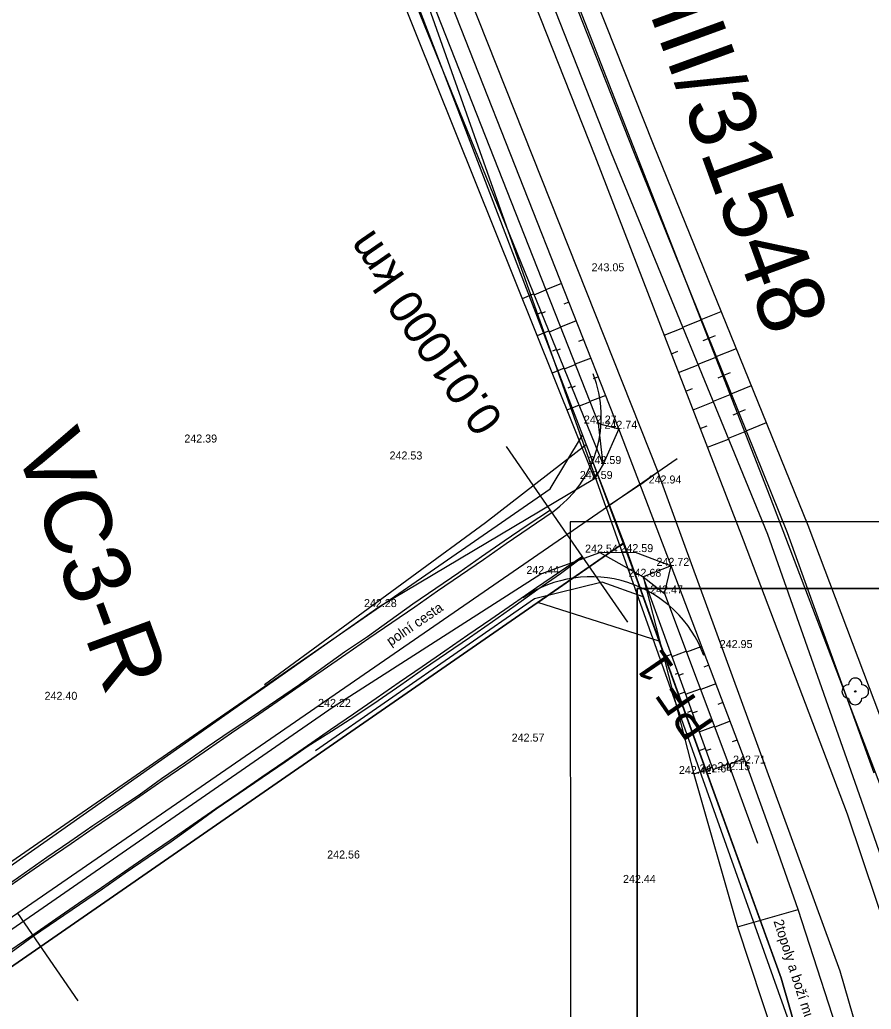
# Model space of a CAD drawing. Extents: x -555887 to -552101, y -1100251 to -1096546.
# Drawn here: x -554780.1 to -554716.3, y -1098267.2 to -1098193.1 of the extents above; entities that cross this region are included whole.
import ezdxf

# ---------------------------------------------------------------- set-up
doc = ezdxf.new("R2010")
doc.units = 0
for name, color, linetype in [('PARCELY_cesty', 7, 'Continuous'), ('PARCELY_silnice', 7, 'Continuous'), ('POLYGONY_rozšíření', 7, 'Continuous'), ('POLYGONY_SITUACE_PF', 7, 'Continuous'), ('POLYGONY_SITUACE_PF_POPISY', 7, 'Continuous'), ('POLYGONY_SITUACE_PO', 7, 'Continuous'), ('ram_VC5', 7, 'Continuous'), ('ROZHLED_parcela_cesty', 7, 'Continuous'), ('ROZHLED_ram_legenda_2', 7, 'Continuous'), ('ROZHLED_trojuhelniky_2', 7, 'Continuous'), ('Výškopis', 7, 'Continuous'), ('ZSST', 7, 'Continuous'), ('zájem', 7, 'Continuous')]:
    doc.layers.add(name, color=color, linetype=linetype)

msp = doc.modelspace()

# ---------------------------------------------------------------- linework, layer by layer
at = {"layer": 'PARCELY_cesty'}
for points in [[(-555432.8, -1098748.4), (-555400.008, -1098712.208), (-555389.921, -1098701.565), (-555373.936, -1098686.469), (-555357.132, -1098672.276), (-555340.17, -1098659.659), (-555299.833, -1098630.198), (-555259.851, -1098600.294), (-555132.603, -1098503.989), (-555074.98, -1098461.38), (-555070.799, -1098455.669), (-555054.379, -1098443.798), (-555047.89, -1098441.68), (-555024.771, -1098425.173), (-554988.252, -1098399.708), (-554740.35, -1098228.23), (-554737.92, -1098224.21)], [(-554741.27, -1098236.74), (-554734.83, -1098232.28), (-554732.18, -1098239.65), (-554741.27, -1098236.74)]]:
    msp.add_lwpolyline(points, dxfattribs=at)
at = {"layer": 'PARCELY_silnice'}
msp.add_lwpolyline([(-554799.78, -1098062.8), (-554737.92, -1098224.21), (-554734.83, -1098232.28), (-554723.03, -1098264.9), (-554699.69, -1098346.16), (-554674.86, -1098437.73), (-554672.03, -1098436.78), (-554666.38, -1098434.92), (-554663.87, -1098434.13), (-554711.41, -1098261.44), (-554723.86, -1098228.82), (-554789.41, -1098060.89)], dxfattribs=at)
at = {"layer": 'POLYGONY_rozšíření'}
for centre, radius, start, end in [((-554745.264, -1098222.852), 8.754, 305.29041, 21.67407), ((-554737.283, -1098243.816), 9, 20.08231, 124.42283)]:
    msp.add_arc(centre, radius, start, end, dxfattribs=at)
at = {"layer": 'POLYGONY_SITUACE_PF'}
for p, q in [((-554739.072, -1098231.645), (-554743.611, -1098225.057)), ((-554734.532, -1098238.232), (-554739.072, -1098231.645)), ((-554775.704, -1098266.603), (-554780.243, -1098260.016))]:
    msp.add_line(p, q, dxfattribs=at)
at = {"layer": 'POLYGONY_SITUACE_PO'}
for p, q in [((-554730.837, -1098225.971), (-554986.543, -1098402.174)), ((-554740.322, -1098229.831), (-554742.07, -1098230.966)), ((-554740.206, -1098229.998), (-554741.922, -1098231.18)), ((-554740.206, -1098229.998), (-554741.922, -1098231.18)), ((-554742.07, -1098230.966), (-554743.79, -1098232.141)), ((-554741.922, -1098231.18), (-554743.637, -1098232.362)), ((-554741.922, -1098231.18), (-554743.637, -1098232.362)), ((-554743.79, -1098232.141), (-554745.497, -1098233.335)), ((-554743.637, -1098232.362), (-554745.353, -1098233.544)), ((-554743.637, -1098232.362), (-554745.353, -1098233.544)), ((-554745.497, -1098233.335), (-554747.199, -1098234.536)), ((-554745.353, -1098233.544), (-554747.068, -1098234.726)), ((-554745.353, -1098233.544), (-554747.068, -1098234.726)), ((-554737.937, -1098233.292), (-554739.652, -1098234.474)), ((-554737.937, -1098233.292), (-554739.652, -1098234.474)), ((-554737.9, -1098233.345), (-554739.562, -1098234.605)), ((-554747.199, -1098234.536), (-554748.922, -1098235.708)), ((-554739.652, -1098234.474), (-554741.368, -1098235.656)), ((-554739.652, -1098234.474), (-554741.368, -1098235.656)), ((-554739.562, -1098234.605), (-554741.279, -1098235.785)), ((-554747.068, -1098234.726), (-554748.784, -1098235.909)), ((-554747.068, -1098234.726), (-554748.784, -1098235.909)), ((-554748.922, -1098235.708), (-554750.642, -1098236.884)), ((-554748.784, -1098235.909), (-554750.499, -1098237.091)), ((-554748.784, -1098235.909), (-554750.499, -1098237.091)), ((-554741.368, -1098235.656), (-554743.083, -1098236.838)), ((-554741.368, -1098235.656), (-554743.083, -1098236.838)), ((-554741.279, -1098235.785), (-554742.978, -1098236.991)), ((-554750.642, -1098236.884), (-554752.335, -1098238.099)), ((-554743.083, -1098236.838), (-554744.799, -1098238.02)), ((-554743.083, -1098236.838), (-554744.799, -1098238.02)), ((-554750.499, -1098237.091), (-554752.215, -1098238.273)), ((-554750.499, -1098237.091), (-554752.215, -1098238.273)), ((-554742.978, -1098236.991), (-554744.674, -1098238.201)), ((-554752.335, -1098238.099), (-554754.028, -1098239.313)), ((-554752.215, -1098238.273), (-554753.93, -1098239.455)), ((-554752.215, -1098238.273), (-554753.93, -1098239.455)), ((-554744.799, -1098238.02), (-554746.514, -1098239.202)), ((-554744.799, -1098238.02), (-554746.514, -1098239.202)), ((-554744.674, -1098238.201), (-554746.383, -1098239.393)), ((-554754.028, -1098239.313), (-554755.76, -1098240.471)), ((-554753.93, -1098239.455), (-554755.646, -1098240.637)), ((-554753.93, -1098239.455), (-554755.646, -1098240.637)), ((-554746.514, -1098239.202), (-554748.23, -1098240.384)), ((-554746.514, -1098239.202), (-554748.23, -1098240.384)), ((-554746.383, -1098239.393), (-554748.104, -1098240.566)), ((-554755.76, -1098240.471), (-554757.445, -1098241.698)), ((-554748.23, -1098240.384), (-554749.945, -1098241.567)), ((-554748.23, -1098240.384), (-554749.945, -1098241.567)), ((-554748.104, -1098240.566), (-554749.83, -1098241.734)), ((-554755.646, -1098240.637), (-554757.361, -1098241.819)), ((-554755.646, -1098240.637), (-554757.361, -1098241.819)), ((-554757.445, -1098241.698), (-554759.133, -1098242.919)), ((-554757.361, -1098241.819), (-554759.077, -1098243.001)), ((-554757.361, -1098241.819), (-554759.077, -1098243.001)), ((-554749.945, -1098241.567), (-554751.661, -1098242.749)), ((-554749.945, -1098241.567), (-554751.661, -1098242.749)), ((-554749.83, -1098241.734), (-554751.533, -1098242.934)), ((-554751.661, -1098242.749), (-554753.376, -1098243.931)), ((-554751.661, -1098242.749), (-554753.376, -1098243.931)), ((-554759.133, -1098242.919), (-554760.85, -1098244.1)), ((-554759.077, -1098243.001), (-554760.792, -1098244.183)), ((-554759.077, -1098243.001), (-554760.792, -1098244.183)), ((-554751.533, -1098242.934), (-554753.242, -1098244.125)), ((-554760.85, -1098244.1), (-554762.586, -1098245.252)), ((-554760.792, -1098244.183), (-554762.508, -1098245.365)), ((-554760.792, -1098244.183), (-554762.508, -1098245.365)), ((-554753.376, -1098243.931), (-554755.092, -1098245.113)), ((-554753.376, -1098243.931), (-554755.092, -1098245.113)), ((-554753.242, -1098244.125), (-554754.976, -1098245.281)), ((-554762.586, -1098245.252), (-554764.323, -1098246.403)), ((-554762.508, -1098245.365), (-554764.223, -1098246.548)), ((-554762.508, -1098245.365), (-554764.223, -1098246.548)), ((-554755.092, -1098245.113), (-554756.807, -1098246.295)), ((-554755.092, -1098245.113), (-554756.807, -1098246.295)), ((-554754.976, -1098245.281), (-554756.731, -1098246.406)), ((-554764.323, -1098246.403), (-554766.039, -1098247.584)), ((-554756.807, -1098246.295), (-554758.523, -1098247.477)), ((-554756.807, -1098246.295), (-554758.523, -1098247.477)), ((-554756.731, -1098246.406), (-554758.491, -1098247.523)), ((-554764.223, -1098246.548), (-554765.939, -1098247.73)), ((-554764.223, -1098246.548), (-554765.939, -1098247.73)), ((-554766.039, -1098247.584), (-554767.739, -1098248.789)), ((-554765.939, -1098247.73), (-554767.654, -1098248.912)), ((-554765.939, -1098247.73), (-554767.654, -1098248.912)), ((-554758.523, -1098247.477), (-554760.238, -1098248.659)), ((-554758.523, -1098247.477), (-554760.238, -1098248.659)), ((-554758.491, -1098247.523), (-554760.198, -1098248.717)), ((-554760.238, -1098248.659), (-554761.954, -1098249.841)), ((-554760.238, -1098248.659), (-554761.954, -1098249.841)), ((-554760.198, -1098248.717), (-554761.92, -1098249.89)), ((-554767.739, -1098248.789), (-554769.456, -1098249.969)), ((-554767.654, -1098248.912), (-554769.37, -1098250.094)), ((-554767.654, -1098248.912), (-554769.37, -1098250.094)), ((-554769.456, -1098249.969), (-554771.151, -1098251.18)), ((-554769.37, -1098250.094), (-554771.085, -1098251.276)), ((-554769.37, -1098250.094), (-554771.085, -1098251.276)), ((-554761.954, -1098249.841), (-554763.669, -1098251.023)), ((-554761.954, -1098249.841), (-554763.669, -1098251.023)), ((-554761.92, -1098249.89), (-554763.642, -1098251.063)), ((-554771.151, -1098251.18), (-554772.89, -1098252.329)), ((-554771.085, -1098251.276), (-554772.801, -1098252.458)), ((-554771.085, -1098251.276), (-554772.801, -1098252.458)), ((-554763.669, -1098251.023), (-554765.385, -1098252.206)), ((-554763.669, -1098251.023), (-554765.385, -1098252.206)), ((-554763.642, -1098251.063), (-554765.363, -1098252.236)), ((-554772.89, -1098252.329), (-554774.621, -1098253.488)), ((-554765.385, -1098252.206), (-554767.1, -1098253.388)), ((-554765.385, -1098252.206), (-554767.1, -1098253.388)), ((-554765.363, -1098252.236), (-554767.056, -1098253.451)), ((-554772.801, -1098252.458), (-554774.516, -1098253.64)), ((-554772.801, -1098252.458), (-554774.516, -1098253.64)), ((-554774.621, -1098253.488), (-554776.326, -1098254.685)), ((-554774.516, -1098253.64), (-554776.232, -1098254.822)), ((-554774.516, -1098253.64), (-554776.232, -1098254.822)), ((-554767.1, -1098253.388), (-554768.816, -1098254.57)), ((-554767.1, -1098253.388), (-554768.816, -1098254.57)), ((-554767.056, -1098253.451), (-554768.748, -1098254.668)), ((-554768.816, -1098254.57), (-554770.531, -1098255.752)), ((-554768.816, -1098254.57), (-554770.531, -1098255.752)), ((-554768.748, -1098254.668), (-554770.462, -1098255.852)), ((-554776.326, -1098254.685), (-554778.056, -1098255.847)), ((-554776.232, -1098254.822), (-554777.947, -1098256.004)), ((-554776.232, -1098254.822), (-554777.947, -1098256.004)), ((-554778.056, -1098255.847), (-554779.747, -1098257.064)), ((-554777.947, -1098256.004), (-554779.663, -1098257.187)), ((-554777.947, -1098256.004), (-554779.663, -1098257.187)), ((-554770.531, -1098255.752), (-554772.246, -1098256.934)), ((-554770.531, -1098255.752), (-554772.246, -1098256.934)), ((-554770.462, -1098255.852), (-554772.178, -1098257.034)), ((-554779.747, -1098257.064), (-554781.461, -1098258.248)), ((-554779.663, -1098257.187), (-554781.378, -1098258.369)), ((-554779.663, -1098257.187), (-554781.378, -1098258.369)), ((-554772.246, -1098256.934), (-554773.962, -1098258.116)), ((-554772.246, -1098256.934), (-554773.962, -1098258.116)), ((-554772.178, -1098257.034), (-554773.887, -1098258.224)), ((-554773.962, -1098258.116), (-554775.677, -1098259.298)), ((-554773.962, -1098258.116), (-554775.677, -1098259.298)), ((-554773.887, -1098258.224), (-554775.604, -1098259.404)), ((-554775.677, -1098259.298), (-554777.393, -1098260.48)), ((-554775.677, -1098259.298), (-554777.393, -1098260.48)), ((-554775.604, -1098259.404), (-554777.326, -1098260.577)), ((-554777.393, -1098260.48), (-554779.108, -1098261.662)), ((-554777.393, -1098260.48), (-554779.108, -1098261.662)), ((-554777.326, -1098260.577), (-554779.047, -1098261.751)), ((-554779.108, -1098261.662), (-554780.824, -1098262.845)), ((-554779.108, -1098261.662), (-554780.824, -1098262.845)), ((-554779.047, -1098261.751), (-554780.741, -1098262.964))]:
    msp.add_line(p, q, dxfattribs=at)
at = {"layer": 'ram_VC5'}
for points in [[(-553898.74, -1098587.46), (-553898.841, -1098230.46), (-554738.841, -1098230.699), (-554738.74, -1098587.699)], [(-553903.741, -1098582.461), (-553903.84, -1098235.461), (-554733.84, -1098235.697), (-554733.741, -1098582.697)]]:
    msp.add_lwpolyline(points, close=True, dxfattribs=at)
for points in [[(-553898.74, -1098587.46), (-553898.841, -1098230.46), (-554738.841, -1098230.699), (-554738.74, -1098587.699), (-553898.74, -1098587.46)], [(-554733.741, -1098582.697), (-554733.84, -1098235.697), (-553903.84, -1098235.461), (-553903.741, -1098582.461), (-554733.741, -1098582.697)]]:
    msp.add_lwpolyline(points, dxfattribs=at)
at = {"layer": 'ROZHLED_parcela_cesty'}
msp.add_lwpolyline([(-554761.76, -1098242.9), (-554745.19, -1098230.74), (-554737.65, -1098224.91), (-554733.37, -1098236.32), (-554736.44, -1098235.23), (-554741.52, -1098236.47), (-554757.94, -1098247.87)], dxfattribs=at)
at = {"layer": 'ROZHLED_trojuhelniky_2'}
for p, q in [((-554776.409, -1098115.833), (-554732.274, -1098226.96)), ((-554736.159, -1098229.619), (-554776.409, -1098115.833)), ((-554733.66, -1098227.96), (-554732.274, -1098226.96)), ((-554733.66, -1098227.96), (-554736.159, -1098229.619)), ((-554736.154, -1098229.634), (-554696.211, -1098341.967))]:
    msp.add_line(p, q, dxfattribs=at)
msp.add_lwpolyline([(-554732.27, -1098226.97), (-554718.64, -1098264.34), (-554696.211, -1098341.967)], dxfattribs=at)
at = {"layer": 'ZSST'}
for p, q in [((-554739.488, -1098212.851), (-554740.667, -1098213.316)), ((-554741.56, -1098213.624), (-554742.439, -1098213.982)), ((-554741.537, -1098213.681), (-554740.664, -1098213.325)), ((-554738.938, -1098214.246), (-554739.331, -1098214.401)), ((-554740.995, -1098215.014), (-554741.29, -1098215.134)), ((-554740.972, -1098215.07), (-554740.686, -1098214.954)), ((-554729.028, -1098215.54), (-554727.525, -1098214.933)), ((-554740.406, -1098216.459), (-554739.565, -1098216.117)), ((-554738.388, -1098215.642), (-554739.568, -1098216.107)), ((-554729.015, -1098215.572), (-554730.422, -1098216.14)), ((-554740.429, -1098216.403), (-554741.322, -1098216.767)), ((-554731.804, -1098216.71), (-554730.409, -1098216.171)), ((-554728.466, -1098216.931), (-554727.965, -1098216.728)), ((-554737.838, -1098217.037), (-554738.231, -1098217.192)), ((-554728.453, -1098216.963), (-554728.919, -1098217.151)), ((-554739.863, -1098217.792), (-554740.163, -1098217.914)), ((-554739.84, -1098217.848), (-554739.565, -1098217.736)), ((-554731.263, -1098218.109), (-554730.789, -1098217.926)), ((-554727.904, -1098218.321), (-554726.396, -1098217.712)), ((-554739.274, -1098219.238), (-554738.465, -1098218.908)), ((-554737.288, -1098218.433), (-554738.469, -1098218.899)), ((-554730.723, -1098219.508), (-554729.271, -1098218.947)), ((-554727.891, -1098218.353), (-554729.284, -1098218.916)), ((-554739.297, -1098219.181), (-554740.205, -1098219.551)), ((-554736.738, -1098219.829), (-554737.131, -1098219.984)), ((-554727.329, -1098219.744), (-554727.791, -1098219.93)), ((-554727.342, -1098219.712), (-554726.839, -1098219.509)), ((-554738.732, -1098220.571), (-554739.036, -1098220.695)), ((-554738.709, -1098220.627), (-554738.445, -1098220.519)), ((-554726.78, -1098221.103), (-554725.267, -1098220.491)), ((-554736.188, -1098221.224), (-554737.37, -1098221.69)), ((-554730.182, -1098220.907), (-554729.689, -1098220.717)), ((-554726.767, -1098221.135), (-554728.145, -1098221.692)), ((-554738.166, -1098221.96), (-554739.088, -1098222.335)), ((-554738.143, -1098222.016), (-554737.366, -1098221.7)), ((-554729.641, -1098222.307), (-554728.132, -1098221.723)), ((-554726.206, -1098222.526), (-554726.662, -1098222.71)), ((-554726.219, -1098222.494), (-554725.714, -1098222.29)), ((-554736.37, -1098226.37), (-554736.72, -1098223.34)), ((-554729.101, -1098223.706), (-554728.589, -1098223.508)), ((-554725.657, -1098223.884), (-554724.138, -1098223.271)), ((-554725.644, -1098223.917), (-554727.007, -1098224.467)), ((-554728.56, -1098225.105), (-554726.994, -1098224.5)), ((-554731.28, -1098234), (-554733.38, -1098234.82)), ((-554728.07, -1098249.48), (-554733.38, -1098234.82)), ((-554731.218, -1098240.788), (-554730.148, -1098240.4)), ((-554728.995, -1098240.037), (-554730.124, -1098240.464)), ((-554731.273, -1098240.637), (-554731.836, -1098240.841)), ((-554730.762, -1098242.048), (-554730.995, -1098242.132)), ((-554730.707, -1098242.198), (-554730.346, -1098242.067)), ((-554728.464, -1098241.44), (-554728.841, -1098241.582)), ((-554730.251, -1098243.458), (-554731.087, -1098243.761)), ((-554730.197, -1098243.609), (-554729.095, -1098243.21)), ((-554727.933, -1098242.842), (-554729.071, -1098243.273)), ((-554727.402, -1098244.245), (-554727.783, -1098244.389)), ((-554729.74, -1098244.868), (-554730.064, -1098244.986)), ((-554729.686, -1098245.019), (-554729.314, -1098244.884)), ((-554726.871, -1098245.648), (-554728.019, -1098246.083)), ((-554729.23, -1098246.279), (-554730.339, -1098246.68)), ((-554729.175, -1098246.429), (-554728.043, -1098246.019)), ((-554726.34, -1098247.051), (-554726.724, -1098247.196)), ((-554728.719, -1098247.689), (-554729.133, -1098247.839)), ((-554728.664, -1098247.84), (-554728.282, -1098247.701)), ((-554725.809, -1098248.454), (-554726.967, -1098248.892)), ((-554728.208, -1098249.099), (-554729.59, -1098249.6)), ((-554728.153, -1098249.25), (-554726.99, -1098248.829)), ((-554726.31, -1098261.05), (-554721.77, -1098259.75))]:
    msp.add_line(p, q, dxfattribs=at)
for points in [[(-554777.06, -1098094.66), (-554758.38, -1098141.35), (-554734.11, -1098202.96), (-554722.58, -1098231.5), (-554716.1, -1098249.51)], [(-554664.42, -1098426.37), (-554675.26, -1098385.42), (-554685.3, -1098349.05), (-554700.53, -1098297.02), (-554708.23, -1098268.73), (-554714.81, -1098247.44), (-554721.01, -1098230.97), (-554732.6, -1098202.44), (-554757.03, -1098140.91), (-554775.48, -1098095.17)], [(-554736.37, -1098226.37), (-554752.72, -1098186.22), (-554769.1, -1098144), (-554783.78, -1098106.95), (-554788.04, -1098095.89)], [(-554788.81, -1098096.59), (-554784.67, -1098107.23), (-554770, -1098144.31), (-554753.44, -1098186.56), (-554737.02, -1098227.49)], [(-554786.79, -1098096.29), (-554782.65, -1098106.8), (-554767.87, -1098143.79), (-554751.44, -1098185.96), (-554736.72, -1098223.34), (-554735.2, -1098223.73)], [(-554777.83, -1098096.16), (-554760.01, -1098141.51), (-554735.79, -1098203.05), (-554724.07, -1098231.63), (-554717.05, -1098251.55), (-554711.12, -1098268.54), (-554702.66, -1098297.07), (-554688.13, -1098349.45), (-554678.03, -1098386.95), (-554667.31, -1098425.58), (-554665.87, -1098427.02)], [(-554761.2, -1098142.08), (-554736.99, -1098203.29), (-554725.88, -1098232.04), (-554718.1, -1098252.58), (-554712.6, -1098268.94), (-554704.01, -1098297.1), (-554689.5, -1098349.87), (-554679.09, -1098387.79), (-554668.31, -1098427.9), (-554666.02, -1098436.06), (-554659.47, -1098460.46)], [(-554664.82, -1098463.03), (-554666.38, -1098457.82), (-554668.66, -1098449.26), (-554681.99, -1098399.65), (-554693.7, -1098356.57), (-554700.22, -1098332.97), (-554701.88, -1098327.39), (-554711.81, -1098291.58), (-554718.04, -1098271.25), (-554721.77, -1098259.75), (-554723.56, -1098254.63), (-554725.67, -1098248.82), (-554731.28, -1098234), (-554735.2, -1098223.73), (-554750.09, -1098185.95)], [(-554735.2, -1098223.73), (-554736.37, -1098226.37), (-554737.02, -1098227.49), (-554753.18, -1098237.09), (-554789.16, -1098262.4), (-554833.26, -1098293.47), (-554862.5, -1098314.49), (-554896.33, -1098337.93), (-554937.06, -1098365.87), (-554951.31, -1098375.41), (-554968.21, -1098386.96), (-554981.09, -1098395.9)], [(-554978.45, -1098399.07), (-554949.34, -1098379.32), (-554917.5, -1098357.35), (-554879.94, -1098331.16), (-554827.91, -1098294.6), (-554786.62, -1098265.32), (-554756.6, -1098244.57), (-554741.04, -1098234.61), (-554736.63, -1098233.01), (-554733.98, -1098232.97), (-554731.28, -1098234)], [(-554736.63, -1098233.01), (-554733.38, -1098234.82), (-554729.59, -1098249.6), (-554726.31, -1098261.05)], [(-554733.38, -1098234.82), (-554731.77, -1098236.07), (-554731.28, -1098234)], [(-554731.77, -1098236.07), (-554726.81, -1098249.31), (-554724.81, -1098254.79)], [(-554726.31, -1098261.05), (-554722.67, -1098272.1), (-554720.49, -1098272.27), (-554718.04, -1098271.25)]]:
    msp.add_lwpolyline(points, dxfattribs=at)
msp.add_circle((-554717.49, -1098243.41), 0.05, dxfattribs=at)
for centre, start, end in [((-554717.488, -1098242.91), 359.79416, 179.79416), ((-554717.99, -1098243.408), 89.79416, 269.79416), ((-554716.99, -1098243.412), 269.79416, 89.79416), ((-554717.492, -1098243.91), 179.79416, 359.79416)]:
    msp.add_arc(centre, 0.5, start, end, dxfattribs=at)
at = {"layer": 'zájem'}
for points in [[(-555057.79, -1098455.7), (-554947.91, -1098379.76), (-554868.79, -1098324.5), (-554807.83, -1098282.81), (-554734.83, -1098232.28), (-554733.03, -1098237.3), (-554723.03, -1098264.9), (-554699.69, -1098346.16), (-554674.86, -1098437.73), (-554672.03, -1098436.78), (-554666.38, -1098434.92), (-554663.87, -1098434.13), (-554584.1, -1098408.07), (-554542.63, -1098394.85), (-554461.77, -1098369.06), (-554380.5, -1098374.37), (-554285.56, -1098379.8), (-554280.9, -1098380.23), (-554271.92, -1098380.9), (-554131.79, -1098402.65)], [(-554131.79, -1098402.65), (-554271.92, -1098380.9), (-554280.9, -1098380.23), (-554285.56, -1098379.8), (-554380.5, -1098374.37), (-554461.77, -1098369.06), (-554542.63, -1098394.85), (-554584.1, -1098408.07), (-554663.87, -1098434.13), (-554666.38, -1098434.92), (-554672.03, -1098436.78), (-554674.86, -1098437.73), (-554699.69, -1098346.16), (-554723.03, -1098264.9), (-554733.03, -1098237.3), (-554734.83, -1098232.28), (-554807.83, -1098282.81), (-554868.79, -1098324.5), (-554947.91, -1098379.76), (-555057.79, -1098455.7)]]:
    msp.add_lwpolyline(points, dxfattribs=at)

# ---------------------------------------------------------------- texts
at = {"layer": 'POLYGONY_SITUACE_PF_POPISY'}
for s, p in [('0.01000 km', (-554743.782, -1098223.046)), ('PF 1', (-554728.035, -1098245.899))]:
    msp.add_text(s, height=2.5, rotation=124.57012, dxfattribs=at).set_placement(p)
at = {"layer": 'ROZHLED_ram_legenda_2'}
for s, height, rotation, p in [('Rozhledové poměry - napojení VC3-R na  silnici III/31548', 4, 289.99372, (-554732.226, -1098075.744)), ('III/31548', 5, 289.99359, (-554732.934, -1098192.526)), ('VC3-R', 5, 290.16468, (-554780.478, -1098225.01))]:
    msp.add_text(s, height=height, rotation=rotation, dxfattribs=at).set_placement(p)
at = {"layer": 'Výškopis'}
for s, p in [('243.05', (-554737.246, -1098211.93)), ('242.27', (-554737.82, -1098223.34)), ('242.74', (-554736.279, -1098223.73)), ('242.39', (-554767.756, -1098224.76)), ('242.53', (-554752.38, -1098226.03)), ('242.59', (-554737.474, -1098226.37)), ('242.59', (-554738.124, -1098227.49)), ('242.94', (-554732.97, -1098227.83)), ('242.54', (-554737.734, -1098233.01)), ('242.59', (-554735.084, -1098232.97)), ('242.72', (-554732.38, -1098234)), ('242.44', (-554742.13, -1098234.61)), ('242.68', (-554734.476, -1098234.82)), ('242.47', (-554732.849, -1098236.07)), ('242.28', (-554754.298, -1098237.09)), ('242.95', (-554727.644, -1098240.16)), ('242.40', (-554778.228, -1098244.04)), ('242.22', (-554757.734, -1098244.57)), ('242.57', (-554743.232, -1098247.17)), ('242.15', (-554727.812, -1098249.31)), ('242.71', (-554726.646, -1098248.82)), ('242.42', (-554730.702, -1098249.6)), ('242.64', (-554729.16, -1098249.48)), ('242.56', (-554757.054, -1098255.93)), ('242.44', (-554734.89, -1098257.76))]:
    msp.add_text(s, height=0.6, dxfattribs=at).set_placement(p)
at = {"layer": 'ZSST'}
for s, rotation, p in [('polní cesta', 34.37747, (-554752.296, -1098240.038)), ('2topoly a boží muka', 287.7967, (-554723.624, -1098260.625))]:
    msp.add_text(s, height=0.75, rotation=rotation, dxfattribs=at).set_placement(p)

doc.saveas('drawing.dxf')
